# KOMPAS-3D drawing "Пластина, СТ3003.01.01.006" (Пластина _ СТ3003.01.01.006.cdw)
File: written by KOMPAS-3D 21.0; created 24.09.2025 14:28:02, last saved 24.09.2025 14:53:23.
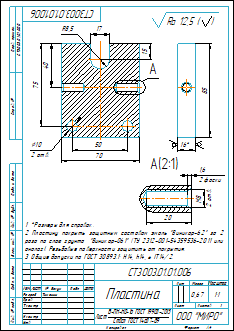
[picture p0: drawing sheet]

Sheet 1: A4, portrait

Document properties: Знак неуказанной шероховатости: 4; Параметр неуказанной шероховатости: Ra 12,5; Масса: 0.669577; Полное имя файла: ..\..\3D\Кронштейн _ СТ3003.01.01.000\Пластина _ СТ3003.01.01.006.m3d

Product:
- Part/product: Пластина  | designation СТ3003.01.01.006
    Материал: Лист$dБ-ПН-НО-16 ГОСТ 19903-2015;Ст3сп ГОСТ 14637-89$ (density 7850 kg/m3)
    Масса: 0.669577

Title block, sheet 1: Наименование: Пластина; designation: СТ3003.01.01.006; Материал: Лист Б-ПН-НО-16 ГОСТ 19903-2015 Ст3сп ГОСТ 14637-89; Масса: 0,67; Количество листов документа: 1; organisation: ООО "МИРО"; Форматы листов документа: A4; stored path: C:\Users\1\Yandex.Disk\Документы\Новая папка\Стапель №2\Стапель _ СТ3003.00.00.000\Опора _ СТ3003.01.00.000\2D\Кронштейн _ СТ3003.01.01.000\Пластина _ СТ3003.01.01.006.cdw; Разработал: Тимонин

Views: Вид 1, Местный разрез 1, Слева, Проекционный вид 2, Выносной элемент 3, Выносной элемент А, Выносной элемент
Referenced files in C:\Users\1\Yandex.Disk\Документы\Новая папка\Стапель №2\Стапель _ СТ3003.00.00.000\Опора _ СТ3003.01.00.000\3D\Кронштейн _ СТ3003.01.01.000\: Пластина _ СТ3003.01.01.006.m3d
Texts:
  Ra 12,5
  Ra 12,5 ( )
  СТ3003.01.01.000
  СТ3003.01.01.006 Пластина
Dimensions and other numbers on the sheet: 40; 75; 17; 8,5; 15; 50; 10; 2 отв.; 70; 85; 16; 1,6; 2 фаски; 8; 20; 1:1; 1; 0,67

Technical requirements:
  *Размеры для справок.
  Пластину покрыть защитным составом эмаль "Виникор-62" за 2
  раза по слою грунта  "Виникор-061" (ТУ 2312-001-54359536-2011 или
  аналог). Резьбовые поверхности защитить от покрытия.
  Общие допуски по ГОСТ 30893.1: Н14, h14, ± IT14/2.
